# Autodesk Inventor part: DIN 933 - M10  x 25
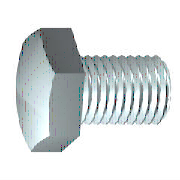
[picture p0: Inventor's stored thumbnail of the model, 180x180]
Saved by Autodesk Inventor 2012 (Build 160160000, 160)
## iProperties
Created: 2004-09
Part Number: DIN 933 - M10  x 25
Material: Standard
Description: Sechskantschraube
Vendor: Autodesk Inc.
Document SubType Name: Modeling
Standard: DIN 933
Designer: Greiling
Size Designation: M10  x 25
Density: 1 g/cm^3
Checked By: Jürgen Kronas
Stock Number: 10-10019
Company: CAD-Verlag
EGR: 1
Classification: un/spsc 31161513
Author: Juergen Kronas
Revision Number: 8
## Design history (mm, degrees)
revolve "Körper" stored, may be unused: angle "d12" = 90 deg
sketch "Skizze2"
  geometry: L1 (0, 9.815)-(8.5, 4.907); L2 (8.5, 4.907)-(8.5, -4.907); L3 (8.5, -4.907)-(0, -9.815); L4 (0, -9.815)-(-8.5, -4.907); L5 (-8.5, -4.907)-(-8.5, 4.907); L6 (-8.5, 4.907)-(0, 9.815); 2 further points
  constraints: 12 end point, 1 coincident, 1 vertical, 11 other
  dimensions: "d11" = 17 distance between parallel lines of L5 L2 (= SW)
extrude "Kopf" join sketch "Skizze2" distance "d3" = 5.8 (= KOH - SD); taper "d4" = 0 deg
revolve "Fase1" stored, may be unused: angle "d21" = 90 deg
node "Volumenkörper1"
node "Volumenkörpern"
node "Oberflächenkörpern"
feature "Gewinde" dims "d15" = 20.5 (= GEL), "d16" = 0
chamfer "Fase2" distance "d6" = 0.92018 (= -0.5 x SPD + 0.5 x GD); stored, may be unused: second distance "d7" = 0.92028 (computed from GUL), angle "d55" = 45 deg
sketch "Skizze1"
  geometry: L1 (0, 7.7)-(0, 4.594); L2 (4.5, 5)-(25, 5); L3 (25, 5)-(25, 0); L4 (25, 0)-(-0.6, 0); L5 (-0.475, 0)-(2.675, 0) reference; L6 (-0.6, 0)-(-0.6, 7.7); L7 (-0.6, 7.7)-(0, 7.7); L8 (4.5, 5)-(3.58, 4.594); L9 (3.58, 4.594)-(0, 4.594); L10 (0, -0.114)-(0, 1.476) reference
  constraints: 16 end point, 2 collinear, 2 perpendicular, 1 parallel
  dimensions: "d0" = 25 distance between parallel lines of L3 L1 (= NLG); "d1" = 20.5 distance from line of L2.start L3 (= GEL); "d2" = 10 diameter of L2 L4 (= GD); "d9" = 0.6001 distance between parallel lines of L6 L1 (computed from SD); "d10" = 15.4 diameter of L7 L4 (= SD2); "d13" = 0.92028 horizontal distance of L2.start L8.end (computed from GAL); "d14" = 9.1881 diameter of L9 L4 (= BDM)
sketch "Skizze4"
  geometry: L1 (-6.4, 8.5)-(-6.4, 9.815); L2 (-6.4, 9.815)-(-5.641, 9.815); L3 (-5.641, 9.815)-(-6.4, 8.5); L4 (-1.185, 0)-(0.005, 0) reference; L5 (-0.6, 9.815)-(-6.4, 9.815) reference; L6 (-6.4, 4.907)-(-6.4, 9.815) reference
  constraints: 6 end point, 2 collinear, 1 perpendicular, 1 vertical
  dimensions: "d5" = 30 deg angle of L3 L1 (= ANG1); "d19" = 17 diameter of L1.start L4 (= SW0)
other parameters: "NLG" = 25 [user parameter; used in 2 equation terms], "GD" = 10 (= NND) [user parameter; used in 2 equation terms], "BDM" = 9.1881 [user parameter; used in 1 equation term], "KOH" = 6.4 [user parameter; used in 1 equation term], "GEL" = 20.5 [user parameter; used in 2 equation terms], "SW" = 17 [user parameter; used in 2 equation terms], "SW0" = 17 [user parameter; used in 1 equation term], "SPD" = 8.15965 (= NND - 1.2269 x TPU) [user parameter; used in 1 equation term], "SD2" = 15.4 [user parameter; used in 1 equation term], "SD" = 0.6 [user parameter; used in 2 equation terms], "ANG1" = 30 deg [user parameter; used in 1 equation term], "GAL" = 0.92018 (= 0.61345 x TPU) [user parameter; used in 1 equation term], "GUL" = 0.92018 (= 0.61345 x TPU) [user parameter; used in 1 equation term], "d8" = 0, "RR" = 0.4 [user parameter], "d20" = -25 (= -NLG), "E0" = 19.635 (= 1.155 x SW) [user parameter], "TPU" = 1.5 [user parameter; used in 5 equation terms], "GD1" = 8.15965 (= THREADDIA - 1.2269 x TPU) [user parameter], "PTC" = 1.5 (= TPU) [user parameter], "TOA" = 30 deg [user parameter]
